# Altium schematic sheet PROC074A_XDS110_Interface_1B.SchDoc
size 431 x 279 mm; Date: Not shown in title block; ApprovedBy: Not shown in title block; CheckedBy: Not shown in title block; Author: Not shown in title block; CompanyName: Not shown in title block; Engineer: Not shown in title block; Organization: Not shown in title block; Address1: Not shown in title block; Address2: Not shown in title block; Address3: Not shown in title block; Address4: Not shown in title block; DocumentNumber: 1; Revision: Use project parameter SCH_Rev; SheetNumber: 12; SheetTotal: 22; PageSetup: Record=PageOptions¦CenterHorizontal=True¦CenterVertical=True¦PrintScale=1.00¦XCorrection=1.00¦YCorrection=1.00¦PrintKind=0¦BorderSize=5000000¦LeftOffset=0¦BottomOffset=0¦Orientation=2¦PaperLength=1000¦PaperWidth=1000¦Scale=100¦PaperSource=15¦PrintQuality=600¦MediaType=1¦DitherType=10¦PaperKind=Letter¦PrintScaleMode=1
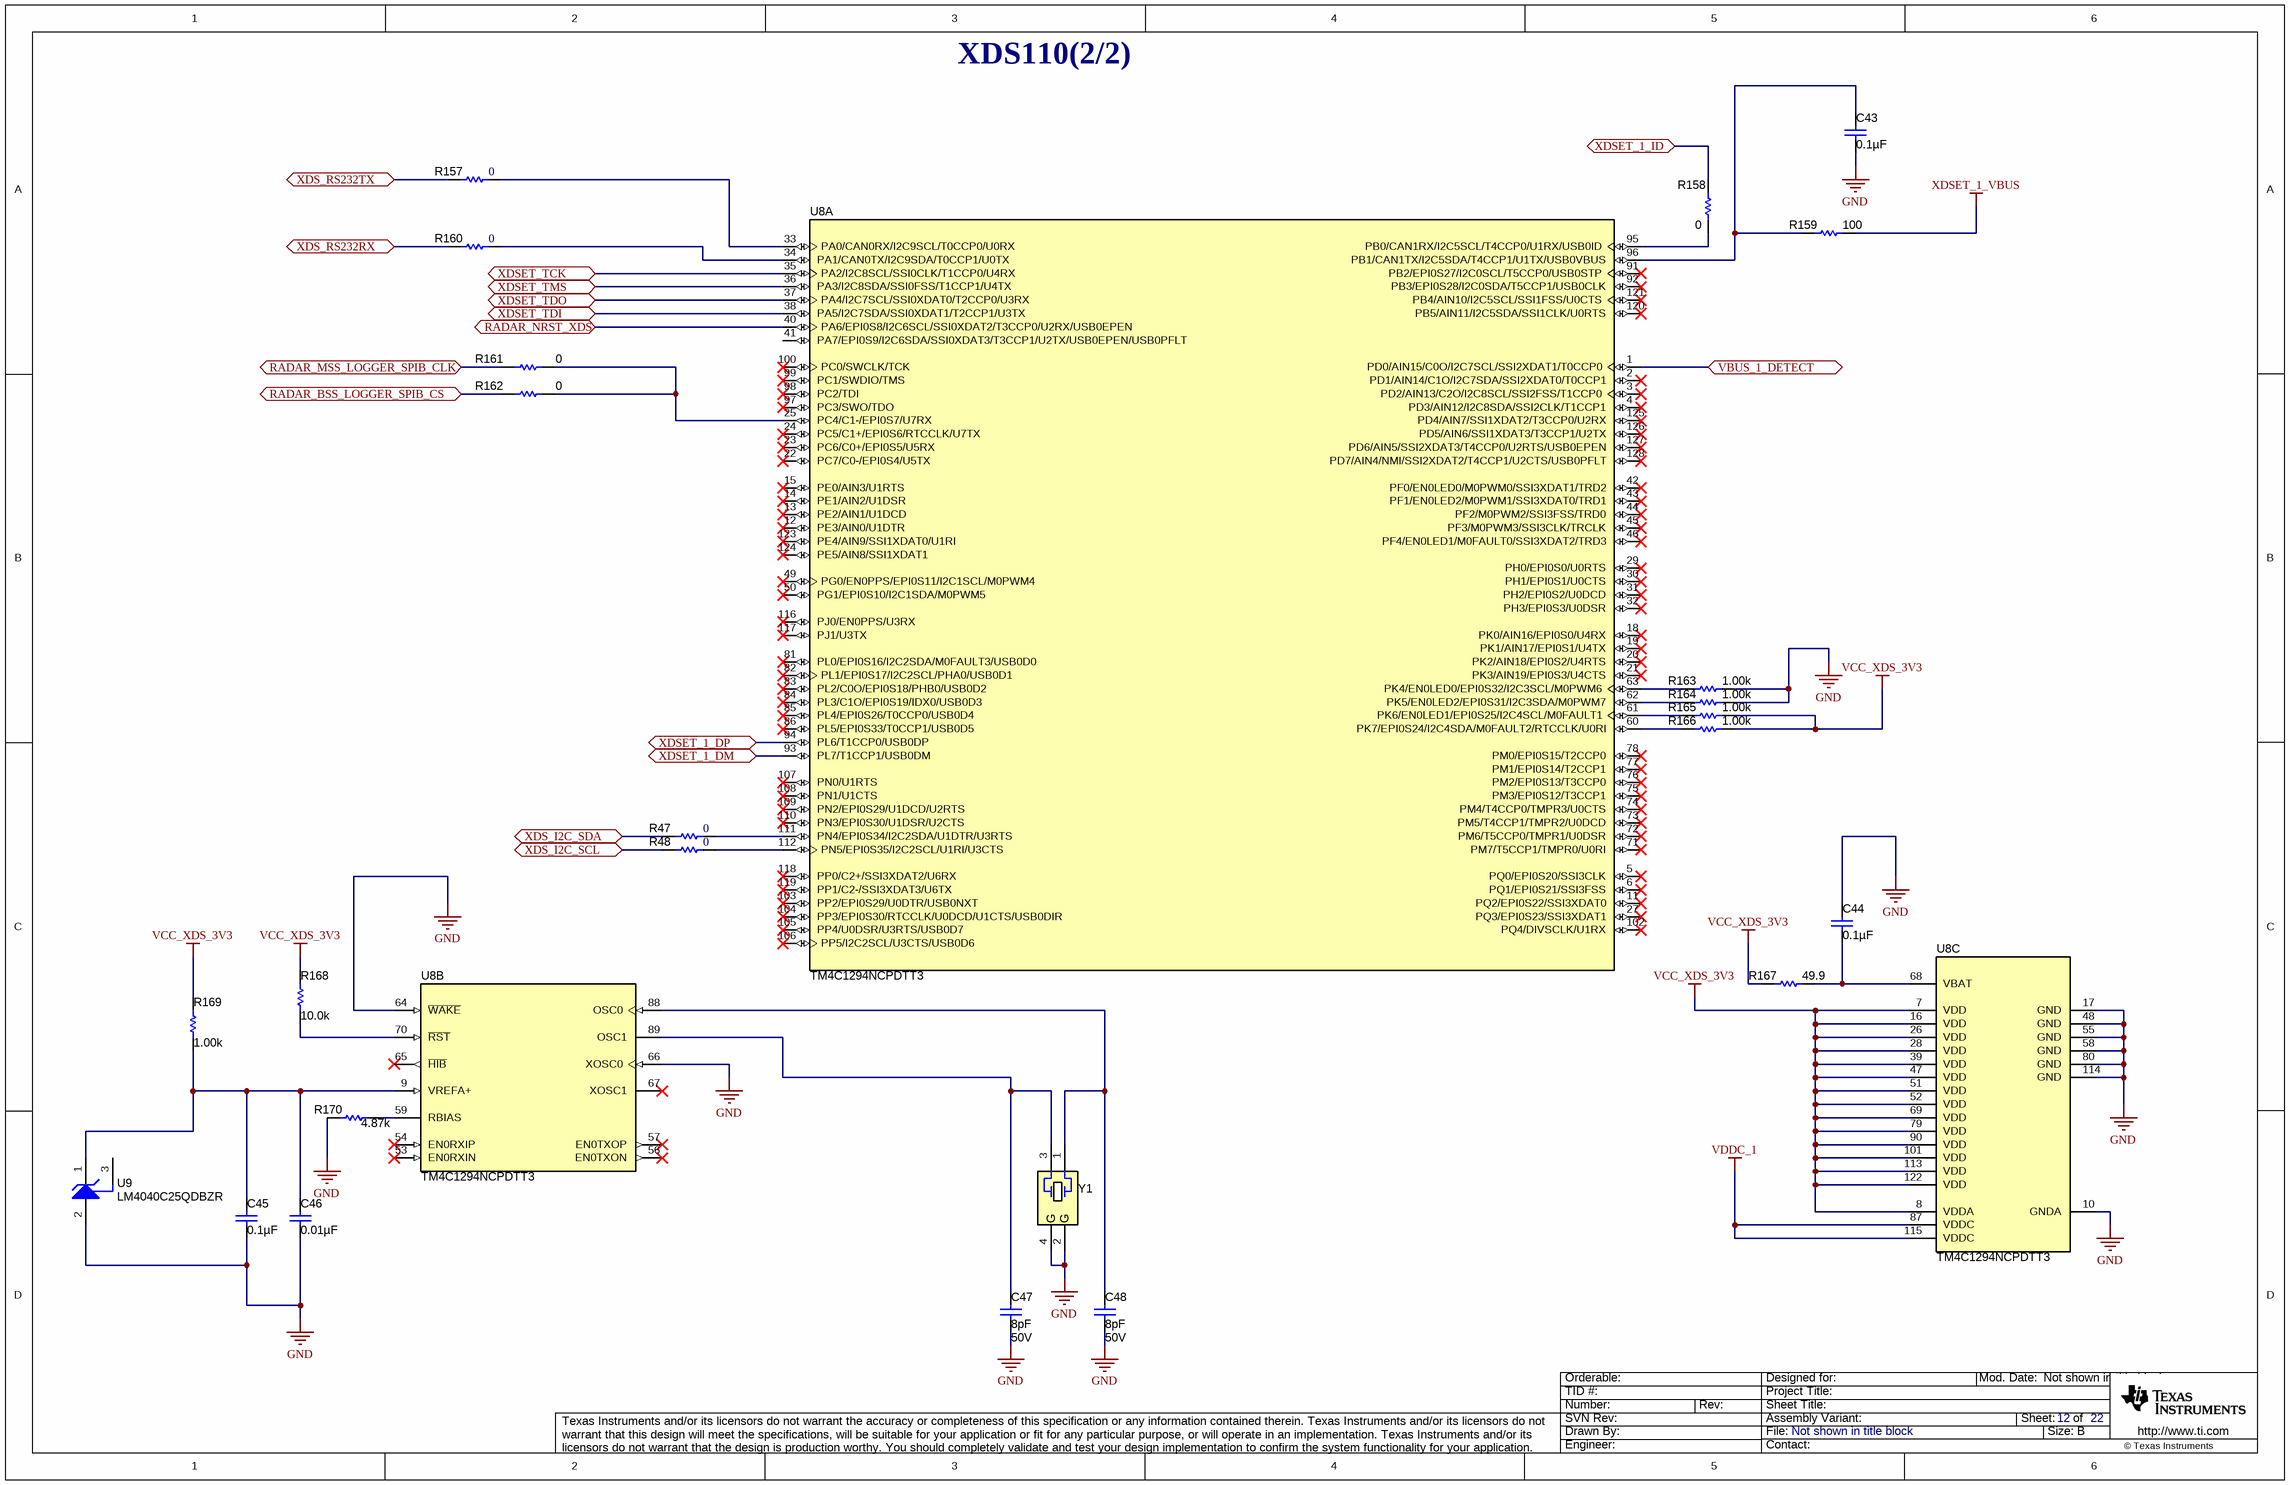
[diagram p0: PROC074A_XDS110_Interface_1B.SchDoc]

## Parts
C43  ValueDisplayed: 0.1µF  [0402L]  (hidden comment: C0402C104K8RACTU)
C44  ValueDisplayed: 0.1µF  [0402L]  (hidden comment: C0402C104K8RACTU)
C45  ValueDisplayed: 0.1µF  [0402L]  (hidden comment: C0402C104K8RACTU)
C46  ValueDisplayed: 0.01µF  [0402L]  (hidden comment: C0402C103K4RACTU)
C47  VDC_V: 50V  ValueDisplayed: 8pF  [0402L]  (hidden comment: GRM1555C1H8R0DA01D)
C48  VDC_V: 50V  ValueDisplayed: 8pF  [0402L]  (hidden comment: GRM1555C1H8R0DA01D)
R47  ValueDisplayed: 0  [0402]  (hidden comment: ERJ-2GE0R00X)
R48  ValueDisplayed: 0  [0402]  (hidden comment: ERJ-2GE0R00X)
R157  ValueDisplayed: 0  [0402]  (hidden comment: ERJ-2GE0R00X)
R158  ValueDisplayed: 0  [0402L]  (hidden comment: ERJ-2GE0R00X)
R159  ValueDisplayed: 100  [0402L]  (hidden comment: ERJ-2GEJ101X)
R160  ValueDisplayed: 0  [0402]  (hidden comment: ERJ-2GE0R00X)
R161  ValueDisplayed: 0  [0201_Silk]  (hidden comment: CRCW02010000Z0ED)
R162  ValueDisplayed: 0  [0201_Silk]  (hidden comment: CRCW02010000Z0ED)
R163  ValueDisplayed: 1.00k  [0402L]  (hidden comment: CRCW04021K00FKED)
R164  ValueDisplayed: 1.00k  [0402L]  (hidden comment: CRCW04021K00FKED)
R165  ValueDisplayed: 1.00k  [0402L]  (hidden comment: CRCW04021K00FKED)
R166  ValueDisplayed: 1.00k  [0402L]  (hidden comment: CRCW04021K00FKED)
R167  ValueDisplayed: 49.9  [0402L]  (hidden comment: CRCW040249R9FKED)
R168  ValueDisplayed: 10.0k  [0402L]  (hidden comment: CRCW040210K0FKED)
R169  ValueDisplayed: 1.00k  [0402L]  (hidden comment: CRCW04021K00FKED)
R170  ValueDisplayed: 4.87k  [0402L]  (hidden comment: CRCW04024K87FKED)
U8  TM4C1294NCPDTT3  [PDT0128A]  (parts A,B,C of 3)
U9  LM4040C25QDBZR  [DBZ0003A_N]
Y1  NX3225SA-16.000M-STD-CRS-2  [NDK_NX3225SA]  (value not drawn)

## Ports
RADAR_BSS_LOGGER_SPIB_CS, RADAR_MSS_LOGGER_SPIB_CLK, RADAR_NRST_XDS, VBUS_1_DETECT, XDS_I2C_SCL, XDS_I2C_SDA, XDS_RS232RX, XDS_RS232TX, XDSET_1_DM, XDSET_1_DP, XDSET_1_ID, XDSET_TCK, XDSET_TDI, XDSET_TDO, XDSET_TMS

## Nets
GND: C43.1 C44.1 C45.1 C46.1 C47.1 C48.1 R163.2 R164.2 R170.1 U8.10(GNDA) U8.17(GND) U8.48(GND) U8.55(GND) U8.58(GND) U8.64(~{WAKE}) U8.66(XOSC0) U8.80(GND) U8.114(GND) U9.2(ANODE) Y1.2(GND) Y1.4(GND)
VCC_XDS_3V3: R165.2 R166.2 R167.2 R168.2 R169.2 U8.7(VDD) U8.8(VDDA) U8.16(VDD) U8.26(VDD) U8.28(VDD) U8.39(VDD) U8.47(VDD) U8.51(VDD) U8.52(VDD) U8.69(VDD) U8.79(VDD) U8.90(VDD) U8.101(VDD) U8.113(VDD) U8.122(VDD)
VDDC_1: U8.87(VDDC) U8.115(VDDC)
XDSET_1_VBUS: R159.2
RADAR_BSS_LOGGER_SPIB_CS: R162.1 ; port RADAR_BSS_LOGGER_SPIB_CS
RADAR_MSS_LOGGER_SPIB_CLK: R161.1 ; port RADAR_MSS_LOGGER_SPIB_CLK
RADAR_NRST_XDS: U8.40(PA6/EPI0S8/I2C6SCL/SSI0XDAT2/T3CCP0/U2RX/USB0EPEN) ; port RADAR_NRST_XDS
VBUS_1_DETECT: U8.1(PD0/AIN15/C0O/I2C7SCL/SSI2XDAT1/T0CCP0) ; port VBUS_1_DETECT
XDS_I2C_SCL: R48.1 ; port XDS_I2C_SCL
XDS_I2C_SDA: R47.1 ; port XDS_I2C_SDA
XDS_RS232RX: R160.1 ; port XDS_RS232RX
XDS_RS232TX: R157.1 ; port XDS_RS232TX
XDSET_1_DM: U8.93(PL7/T1CCP1/USB0DM) ; port XDSET_1_DM
XDSET_1_DP: U8.94(PL6/T1CCP0/USB0DP) ; port XDSET_1_DP
XDSET_1_ID: R158.2 ; port XDSET_1_ID
XDSET_TCK: U8.35(PA2/I2C8SCL/SSI0CLK/T1CCP0/U4RX) ; port XDSET_TCK
XDSET_TDI: U8.38(PA5/I2C7SDA/SSI0XDAT1/T2CCP1/U3TX) ; port XDSET_TDI
XDSET_TDO: U8.37(PA4/I2C7SCL/SSI0XDAT0/T2CCP0/U3RX) ; port XDSET_TDO
XDSET_TMS: U8.36(PA3/I2C8SDA/SSI0FSS/T1CCP1/U4TX) ; port XDSET_TMS
NetC43_2: C43.2 R159.1 U8.96(PB1/CAN1TX/I2C5SDA/T4CCP1/U1TX/USB0VBUS)
NetC44_2: C44.2 R167.1 U8.68(VBAT)
NetC45_2: C45.2 C46.2 R169.1 U8.9(VREFA+) U9.1(CATHODE)
NetC47_2: C47.2 U8.89(OSC1) Y1.3
NetC48_2: C48.2 U8.88(OSC0) Y1.1
NetR47_2: R47.2 U8.111(PN4/EPI0S34/I2C2SDA/U1DTR/U3RTS)
NetR48_2: R48.2 U8.112(PN5/EPI0S35/I2C2SCL/U1RI/U3CTS)
NetR157_2: R157.2 U8.33(PA0/CAN0RX/I2C9SCL/T0CCP0/U0RX)
NetR158_1: R158.1 U8.95(PB0/CAN1RX/I2C5SCL/T4CCP0/U1RX/USB0ID)
NetR160_2: R160.2 U8.34(PA1/CAN0TX/I2C9SDA/T0CCP1/U0TX)
NetR161_2: R161.2 R162.2 U8.25(PC4/C1-/EPI0S7/U7RX)
NetR163_1: R163.1 U8.63(PK4/EN0LED0/EPI0S32/I2C3SCL/M0PWM6)
NetR164_1: R164.1 U8.62(PK5/EN0LED2/EPI0S31/I2C3SDA/M0PWM7)
NetR165_1: R165.1 U8.61(PK6/EN0LED1/EPI0S25/I2C4SCL/M0FAULT1)
NetR166_1: R166.1 U8.60(PK7/EPI0S24/I2C4SDA/M0FAULT2/RTCCLK/U0RI)
NetR168_1: R168.1 U8.70(~{RST})
NetR170_2: R170.2 U8.59(RBIAS)

Not connected (* = marked no-connect by the designer): U8 2(PD1/AIN14/C1O/I2C7SDA/SSI2XDAT0/T0CCP1)* 3(PD2/AIN13/C2O/I2C8SCL/SSI2FSS/T1CCP0)* 4(PD3/AIN12/I2C8SDA/SSI2CLK/T1CCP1)* 5(PQ0/EPI0S20/SSI3CLK)* 6(PQ1/EPI0S21/SSI3FSS)* 11(PQ2/EPI0S22/SSI3XDAT0)* 12(PE3/AIN0/U1DTR)* 13(PE2/AIN1/U1DCD)* 14(PE1/AIN2/U1DSR)* 15(PE0/AIN3/U1RTS)* 18(PK0/AIN16/EPI0S0/U4RX)* 19(PK1/AIN17/EPI0S1/U4TX)* 20(PK2/AIN18/EPI0S2/U4RTS)* 21(PK3/AIN19/EPI0S3/U4CTS)* 22(PC7/C0-/EPI0S4/U5TX)* 23(PC6/C0+/EPI0S5/U5RX)* 24(PC5/C1+/EPI0S6/RTCCLK/U7TX)* 27(PQ3/EPI0S23/SSI3XDAT1)* 29(PH0/EPI0S0/U0RTS)* 30(PH1/EPI0S1/U0CTS)* 31(PH2/EPI0S2/U0DCD)* 32(PH3/EPI0S3/U0DSR)* 41(PA7/EPI0S9/I2C6SDA/SSI0XDAT3/T3CCP1/U2TX/USB0EPEN/USB0PFLT) 42(PF0/EN0LED0/M0PWM0/SSI3XDAT1/TRD2)* 43(PF1/EN0LED2/M0PWM1/SSI3XDAT0/TRD1)* 44(PF2/M0PWM2/SSI3FSS/TRD0)* 45(PF3/M0PWM3/SSI3CLK/TRCLK)* 46(PF4/EN0LED1/M0FAULT0/SSI3XDAT2/TRD3)* 49(PG0/EN0PPS/EPI0S11/I2C1SCL/M0PWM4)* 50(PG1/EPI0S10/I2C1SDA/M0PWM5)* 53(EN0RXIN)* 54(EN0RXIP)* 56(EN0TXON)* 57(EN0TXOP)* 65(~{HIB})* 67(XOSC1)* 71(PM7/T5CCP1/TMPR0/U0RI)* 72(PM6/T5CCP0/TMPR1/U0DSR)* 73(PM5/T4CCP1/TMPR2/U0DCD)* 74(PM4/T4CCP0/TMPR3/U0CTS)* 75(PM3/EPI0S12/T3CCP1)* 76(PM2/EPI0S13/T3CCP0)* 77(PM1/EPI0S14/T2CCP1)* 78(PM0/EPI0S15/T2CCP0)* 81(PL0/EPI0S16/I2C2SDA/M0FAULT3/USB0D0)* 82(PL1/EPI0S17/I2C2SCL/PHA0/USB0D1)* 83(PL2/C0O/EPI0S18/PHB0/USB0D2)* 84(PL3/C1O/EPI0S19/IDX0/USB0D3)* 85(PL4/EPI0S26/T0CCP0/USB0D4)* 86(PL5/EPI0S33/T0CCP1/USB0D5)* 91(PB2/EPI0S27/I2C0SCL/T5CCP0/USB0STP)* 92(PB3/EPI0S28/I2C0SDA/T5CCP1/USB0CLK)* 97(PC3/SWO/TDO)* 98(PC2/TDI)* 99(PC1/SWDIO/TMS)* 100(PC0/SWCLK/TCK)* 102(PQ4/DIVSCLK/U1RX)* 103(PP2/EPI0S29/U0DTR/USB0NXT)* 104(PP3/EPI0S30/RTCCLK/U0DCD/U1CTS/USB0DIR)* 105(PP4/U0DSR/U3RTS/USB0D7)* 106(PP5/I2C2SCL/U3CTS/USB0D6)* 107(PN0/U1RTS)* 108(PN1/U1CTS)* 109(PN2/EPI0S29/U1DCD/U2RTS)* 110(PN3/EPI0S30/U1DSR/U2CTS)* 116(PJ0/EN0PPS/U3RX)* 117(PJ1/U3TX)* 118(PP0/C2+/SSI3XDAT2/U6RX)* 119(PP1/C2-/SSI3XDAT3/U6TX)* 120(PB5/AIN11/I2C5SDA/SSI1CLK/U0RTS)* 121(PB4/AIN10/I2C5SCL/SSI1FSS/U0CTS)* 123(PE4/AIN9/SSI1XDAT0/U1RI)* 124(PE5/AIN8/SSI1XDAT1)* 125(PD4/AIN7/SSI1XDAT2/T3CCP0/U2RX)* 126(PD5/AIN6/SSI1XDAT3/T3CCP1/U2TX)* 127(PD6/AIN5/SSI2XDAT3/T4CCP0/U2RTS/USB0EPEN)* 128(PD7/AIN4/NMI/SSI2XDAT2/T4CCP1/U2CTS/USB0PFLT)*; U9 3(NC)

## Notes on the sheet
- XDS110(2/2)

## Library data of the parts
C43-C45 = CMP-0078241-1: CAP, CERM, 0.1 µF, 10 V,+/- 10%, X7R, 0402; Manufacturer: Kemet; TaMin_C: -55°C; Polarized: N; SizeAreaWB_mm2: 3; U/M: EA; Value: 0.1uF; TaMax_C: 125°C; SizeZ_mm: 0.6; SizeX_mm: 1; SizeY_mm: 0.5; Cap_Case: 0402; Value2: 10V; CompType: Capacitor; Cap_F: 100nF; AEC Category: Q200
C46 = CMP-0078218-1: CAP, CERM, 0.01 µF, 16 V,+/- 10%, X7R, 0402; Manufacturer: Kemet; TaMin_C: -55°C; Polarized: N; Green_Lifecycle: Active; SizeAreaWB_mm2: 3; Green_REACh: Passed; U/M: EA; Value: 0.01uF; TaMax_C: 125°C; SizeZ_mm: 0.6; SizeX_mm: 1; SizeY_mm: 0.5; Cap_Case: 0402; Value2: 16V; CompType: Capacitor; Cap_F: 10nF; AEC Category: Q200
C47 C48 = CMP-0006494-2: CAP, CERM, 8 pF, 50 V, +/- 6%, C0G/NP0, 0402; Manufacturer: MuRata; TaMin_C: -55°C; Polarized: N; SizeAreaWB_mm2: 3; Value1: Unknown; U/M: EA; Value: 8pF; TaMax_C: 125°C; SizeZ_mm: 0.6; SizeX_mm: 1; SizeY_mm: 0.5; Cap_Case: 0402; CompType: Capacitor; AEC Category: Q200
R47 R48 R157 R160 = CMP-0026992-3: RES, 0, 5%, 0.1 W, AEC-Q200 Grade 0, 0402; Manufacturer: Panasonic; Power_W: 100mW; TempCo: 600 ppm/C; Value_Code: 0000; Value: 0; EIA_Code: E24; SizeX_mm: 1; SizeY_mm: 0.5; SizeZ_mm: 0.6; Value2: 0.1W; AEC Qualified: Y; VDC_V: 50V; AEC Category: Q200; SizeAreaWB_mm2: 3
R158 = CMP-0026992-2: RES, 0, 5%, 0.063 W, 0402; Manufacturer: Panasonic; Power_W: 63mW; TempCo: 600 ppm/C; Value_Code: 0000; U/M: EA; Value: 0; EIA_Code: E24; SizeX_mm: 1; SizeY_mm: 0.5; SizeZ_mm: 0.6; Value2: 0.063W; VDC_V: 50V; AEC Category: Q200
R159 = CMP-0026993-2: RES, 100, 5%, 0.1 W, AEC-Q200 Grade 0, 0402; Manufacturer: Panasonic; Power_W: 100mW; TempCo: 200 ppm/C; Value_Code: 100R; U/M: EA; Value: 100; EIA_Code: E24; SizeX_mm: 1; SizeY_mm: 0.5; SizeZ_mm: 0.6; Value2: 0.1W; AEC Qualified: Y; AEC Grade: 0; AEC Category: Q200
R161 = CMP-0027008-3: RES, 0, 5%, 0.05 W, 0201; Manufacturer: Vishay-Dale; Power_W: 50mW; TempCo: ppm/C; Value_Code: 0000; U/M: EA; Value: 0; EIA_Code: E24; SizeX_mm: 0.6; SizeY_mm: 0.3; SizeZ_mm: 0.26; Value2: 0.05W; SizeArea_mm2: 0.18; AEC Qualified: N; AEC Category: Q200
R162 = CMP-0027008-3: RES, 0, 5%, 0.05 W, 0201; Manufacturer: Vishay-Dale; Power_W: 50mW; TempCo: ppm/C; Value_Code: 0000; U/M: EA; Value: 0; EIA_Code: E24; SizeX_mm: 0.6; SizeY_mm: 0.3; SizeZ_mm: 0.26; Value2: 0.05W; SizeArea_mm2: 0.18; CompType: Resistor; AEC Qualified: N; AEC Category: Q200; INSTALLATION: DNP
R163-R166 R169 = CMP-0026071-2: RES, 1.00 k, 1%, 0.063 W, 0402; Manufacturer: Vishay-Dale; Power_W: 63mW; TempCo: 100 ppm/C; Value_Code: 1k00; U/M: EA; Value: 1.00k; EIA_Code: E96; Res_ohm: 1k; SizeX_mm: 1; SizeY_mm: 0.5; SizeZ_mm: 0.6; Value2: 0.063W; VDC_V: 50V; AEC Category: Q200
R167 = CMP-0026404-1: RES, 49.9, 1%, 0.063 W, 0402; Manufacturer: Vishay-Dale; Power_W: 63mW; TempCo: 100 ppm/C; Value_Code: 49R9; U/M: EA; Value: 49.9; EIA_Code: E96; SizeX_mm: 1; SizeY_mm: 0.5; SizeZ_mm: 0.6; Value2: 0.063W; VDC_V: 50V; AEC Category: Q200
R168 = CMP-0025958-2: RES, 10.0 k, 1%, 0.063 W, 0402; Manufacturer: Vishay-Dale; Power_W: 63mW; TempCo: 100 ppm/C; Value_Code: 10k0; U/M: EA; Value: 10.0k; EIA_Code: E96; Res_ohm: 10k; SizeX_mm: 1; SizeY_mm: 0.5; SizeZ_mm: 0.6; Value2: 0.063W; VDC_V: 50V; AEC Category: Q200
R170 = CMP-0026413-1: RES, 4.87 k, 1%, 0.063 W, 0402; Manufacturer: Vishay-Dale; Power_W: 63mW; TempCo: 100 ppm/C; Value_Code: 4k87; U/M: EA; Value: 4.87k; EIA_Code: E96; SizeX_mm: 1; SizeY_mm: 0.5; SizeZ_mm: 0.6; Value2: 0.063W; VDC_V: 50V; AEC Category: Q200
U8 = CMP-0029856-2: Tiva C Series Microcontroller, 1024 KB Flash, 256 KB SRAM, 12 Bit, 20 Channels, -40 to 105 degC, 128-Pin TQFP (PDT), Green (RoHS & no Sb/Br), Tray; Manufacturer: Texas Instruments; ADC Channels: 20; CPU: ARM Cortex-M4; Flash: 1024 KB; ADC Resolution: 12 Bits; Max Speed: 120 MHz; SRAM: 256 KB; SizeAreaWB_mm2: 324.0; SizeArea_mm2: 256.0; SizeX_mm: 16.0; SizeZ_mm: 1.2; CompType: IC
U9 = CMP-0033001-1: Precision Micropower Shunt Voltage Reference, 0.5% accuracy, 2.5 V, 15 ppm / degC, 15 mA, -40 to 125 degC, 3-pin SOT-23 (DBZ), Green (RoHS & no Sb/Br); Manufacturer: Texas Instruments; Initial Accuracy @ 25/deg C(%): 0.5; Temp Coeff(Typ)(ppm/ degree C): 15; Temp Coeff(Max)(ppm/ degree C): 100; Rating: Catalog; Min Iz for Regulation(uA): 75; VO(V): 2.5
Y1 = CMP-0078214-2: Crystal, 16 MHz, 15 ppm, 8 pF, AEC-Q200 Grade 1, SMD; Manufacturer: NDK; TaMin_C: -40°C; Frequency Tolerance: 10 ppm; Frequency Stability: 150 ppm; Load Capacitance: 7.36 pF; Frequency_Fixed: 16MHz; TaMax_C: 125°C; AEC Qualified: N; AEC Grade: 1; AEC Category: Q200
